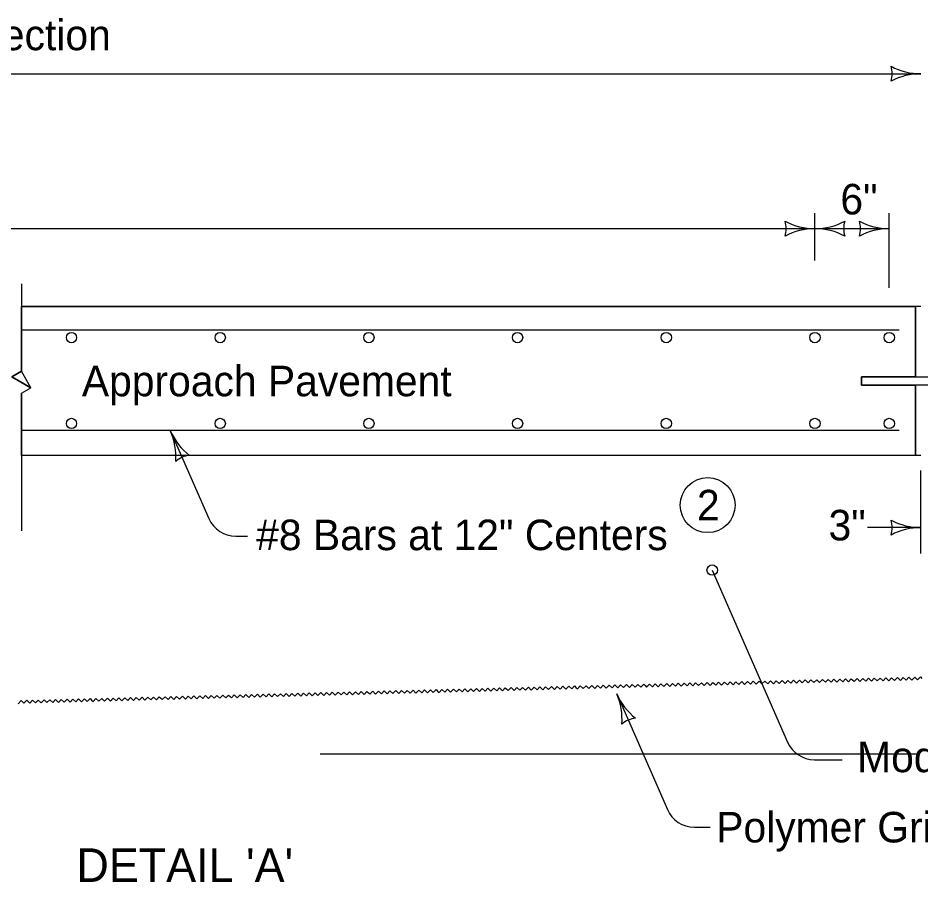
# Model space of a CAD drawing. Extents: x -2135039 to -2120895, y -2139150 to -2136566.
# Drawn here: x -2130191 to -2129599, y -2137809 to -2137243 of the extents above; entities that cross this region are included whole.
import ezdxf

# ---------------------------------------------------------------- set-up
doc = ezdxf.new("R2010")
doc.units = 0
for name, color, linetype in [('dsnStdLabel', 7, 'Continuous'), ('dsnStdLineWork', 7, 'Continuous'), ('dsnStdNote', 7, 'Continuous'), ('Level 2', 7, 'Continuous'), ('Level 3', 7, 'Continuous'), ('Level 4', 7, 'Continuous'), ('Level 5', 7, 'Continuous')]:
    doc.layers.add(name, color=color, linetype=linetype)

msp = doc.modelspace()

# ---------------------------------------------------------------- linework, layer by layer
at = {"layer": 'dsnStdLabel'}
for p, q in [((-2130208.33, -2137279.26), (-2129598.95, -2137279.26)), ((-2129668.41, -2137401.68), (-2129668.41, -2137370.66)), ((-2129619.69, -2137419.41), (-2129619.69, -2137370.66)), ((-2129668.41, -2137380.75), (-2130237.27, -2137380.75)), ((-2129619.69, -2137380.75), (-2129668.41, -2137380.75)), ((-2130090.67, -2137513.32), (-2130065.57, -2137570.65)), ((-2129598.95, -2137593.64), (-2129598.95, -2137539.26)), ((-2129598.95, -2137576.57), (-2129634, -2137576.57)), ((-2130047.94, -2137582.18), (-2130040.18, -2137582.18)), ((-2129735.72, -2137604.39), (-2129686.37, -2137717.13)), ((-2129798.28, -2137685.5), (-2129765.09, -2137761.33)), ((-2129668.74, -2137728.65), (-2129650.5, -2137728.65)), ((-2129747.46, -2137772.85), (-2129737.16, -2137772.85))]:
    msp.add_line(p, q, dxfattribs=at)
msp.add_circle((-2129735.72, -2137604.39), 3.42, dxfattribs=at)
for centre, radius, start, end in [((-2129633.79, -2137279.26), 16.05, 342.26665, 17.73335), ((-2129598.95, -2137237.71), 41.55, 241.92751, 270), ((-2129598.95, -2137320.81), 41.55, 90, 118.07249), ((-2129703.25, -2137380.75), 16.05, 342.26665, 17.73335), ((-2129668.41, -2137339.19), 41.55, 241.92751, 270), ((-2129668.41, -2137339.19), 41.55, 270, 298.07249), ((-2129633.57, -2137380.75), 16.05, 162.26665, 197.73335), ((-2129654.53, -2137380.75), 16.05, 342.26665, 17.73335), ((-2129619.69, -2137339.19), 41.55, 241.92751, 270), ((-2129668.41, -2137422.3), 41.55, 90, 118.07249), ((-2129668.41, -2137422.3), 41.55, 61.92751, 90), ((-2129619.69, -2137422.3), 41.55, 90, 118.07249), ((-2130052.6, -2137496.66), 41.55, 203.64012, 231.71261), ((-2130128.73, -2137529.98), 41.55, 355.56763, 23.64012), ((-2130076.69, -2137545.24), 16.05, 95.90677, 131.37347), ((-2130047.94, -2137562.93), 19.25, 203.64012, 270), ((-2129633.79, -2137576.57), 16.05, 342.26665, 17.73335), ((-2129598.95, -2137535.02), 41.55, 241.92751, 270), ((-2129598.95, -2137618.13), 41.55, 90, 118.07249), ((-2129760.22, -2137668.83), 41.55, 203.64012, 231.71261), ((-2129836.35, -2137702.16), 41.55, 355.56763, 23.64012), ((-2129784.31, -2137717.41), 16.05, 95.90677, 131.37347), ((-2129668.74, -2137709.41), 19.25, 203.64012, 270), ((-2129747.46, -2137753.61), 19.25, 203.64012, 270)]:
    msp.add_arc(centre, radius, start, end, dxfattribs=at)
at = {"layer": 'dsnStdLineWork'}
for p, q in [((-2130188.44, -2137416.94), (-2130188.44, -2137474.16)), ((-2129598.95, -2137431.83), (-2130188.44, -2137431.83)), ((-2129637.92, -2137483.26), (-2129637.92, -2137477.85)), ((-2129637.92, -2137477.85), (-2129559.97, -2137477.85)), ((-2129559.97, -2137483.26), (-2129637.92, -2137483.26)), ((-2130188.44, -2137488.6), (-2130188.44, -2137578.71))]:
    msp.add_line(p, q, dxfattribs=at)
for points in [[(-2130188.44, -2137488.6), (-2130182.18, -2137485), (-2130194.69, -2137477.76), (-2130188.44, -2137474.16)], [(-2129688.98, -2137677.73), (-2129688.01, -2137678.65), (-2129686.17, -2137676.72), (-2129684.23, -2137678.55), (-2129682.39, -2137676.62), (-2129680.45, -2137678.45), (-2129678.62, -2137676.52), (-2129676.67, -2137678.36), (-2129674.84, -2137676.42), (-2129672.9, -2137678.25), (-2129671.06, -2137676.32), (-2129669.12, -2137678.16), (-2129667.27, -2137676.22), (-2129665.34, -2137678.06), (-2129663.49, -2137676.12), (-2129661.56, -2137677.96), (-2129659.72, -2137676.02), (-2129657.78, -2137677.86), (-2129655.94, -2137675.92), (-2129654, -2137677.76), (-2129652.16, -2137675.83), (-2129650.22, -2137677.66), (-2129648.38, -2137675.73), (-2129646.44, -2137677.56), (-2129644.6, -2137675.63), (-2129643.64, -2137676.55)], [(-2129643.64, -2137676.55), (-2129642.67, -2137677.47), (-2129640.83, -2137675.53), (-2129638.89, -2137677.37), (-2129637.05, -2137675.43), (-2129635.11, -2137677.27), (-2129633.27, -2137675.33), (-2129631.33, -2137677.17), (-2129629.49, -2137675.23), (-2129627.55, -2137677.07), (-2129625.71, -2137675.14), (-2129623.78, -2137676.97), (-2129621.94, -2137675.04), (-2129619.99, -2137676.87), (-2129618.15, -2137674.94), (-2129616.22, -2137676.78), (-2129614.38, -2137674.84), (-2129612.44, -2137676.68), (-2129610.6, -2137674.74), (-2129608.66, -2137676.58), (-2129606.82, -2137674.64), (-2129604.88, -2137676.48), (-2129603.04, -2137674.54), (-2129601.11, -2137676.38), (-2129599.26, -2137674.44), (-2129598.3, -2137675.36)], [(-2129915.68, -2137683.65), (-2129914.72, -2137684.57), (-2129912.87, -2137682.64), (-2129910.93, -2137684.48), (-2129909.09, -2137682.54), (-2129907.16, -2137684.37), (-2129905.32, -2137682.44), (-2129903.38, -2137684.28), (-2129901.54, -2137682.33), (-2129899.6, -2137684.17), (-2129897.76, -2137682.24), (-2129895.82, -2137684.08), (-2129893.98, -2137682.14), (-2129892.05, -2137683.97), (-2129890.2, -2137682.04), (-2129888.26, -2137683.88), (-2129886.43, -2137681.94), (-2129884.49, -2137683.78), (-2129882.65, -2137681.84), (-2129880.71, -2137683.68), (-2129878.86, -2137681.74), (-2129876.93, -2137683.58), (-2129875.09, -2137681.65), (-2129873.15, -2137683.48), (-2129871.31, -2137681.55), (-2129870.34, -2137682.47)], [(-2129870.34, -2137682.47), (-2129869.37, -2137683.39), (-2129867.53, -2137681.45), (-2129865.59, -2137683.29), (-2129863.75, -2137681.35), (-2129861.81, -2137683.19), (-2129859.97, -2137681.25), (-2129858.04, -2137683.09), (-2129856.2, -2137681.15), (-2129854.26, -2137682.99), (-2129852.42, -2137681.05), (-2129850.48, -2137682.89), (-2129848.64, -2137680.96), (-2129846.7, -2137682.79), (-2129844.86, -2137680.86), (-2129842.92, -2137682.7), (-2129841.08, -2137680.76), (-2129839.14, -2137682.6), (-2129837.31, -2137680.66), (-2129835.37, -2137682.5), (-2129833.53, -2137680.56), (-2129831.59, -2137682.4), (-2129829.75, -2137680.46), (-2129827.81, -2137682.3), (-2129825.97, -2137680.36), (-2129825, -2137681.28)], [(-2129825, -2137681.28), (-2129824.03, -2137682.2), (-2129822.19, -2137680.26), (-2129820.25, -2137682.1), (-2129818.41, -2137680.16), (-2129816.47, -2137682), (-2129814.63, -2137680.07), (-2129812.7, -2137681.9), (-2129810.85, -2137679.97), (-2129808.92, -2137681.81), (-2129807.08, -2137679.87), (-2129805.14, -2137681.71), (-2129803.3, -2137679.77), (-2129801.36, -2137681.61), (-2129799.52, -2137679.67), (-2129797.58, -2137681.51), (-2129795.74, -2137679.57), (-2129793.81, -2137681.41), (-2129791.96, -2137679.48), (-2129790.03, -2137681.31), (-2129788.19, -2137679.38), (-2129786.25, -2137681.21), (-2129784.41, -2137679.28), (-2129782.47, -2137681.12), (-2129780.63, -2137679.18), (-2129779.66, -2137680.1)], [(-2129779.66, -2137680.1), (-2129778.69, -2137681.02), (-2129776.85, -2137679.08), (-2129774.91, -2137680.92), (-2129773.07, -2137678.98), (-2129771.13, -2137680.82), (-2129769.29, -2137678.89), (-2129767.35, -2137680.72), (-2129765.52, -2137678.79), (-2129763.57, -2137680.62), (-2129761.74, -2137678.68), (-2129759.8, -2137680.53), (-2129757.96, -2137678.59), (-2129756.02, -2137680.43), (-2129754.18, -2137678.49), (-2129752.24, -2137680.32), (-2129750.4, -2137678.39), (-2129748.46, -2137680.23), (-2129746.62, -2137678.29), (-2129744.68, -2137680.13), (-2129742.84, -2137678.19), (-2129740.91, -2137680.03), (-2129739.07, -2137678.09), (-2129737.13, -2137679.93), (-2129735.29, -2137678), (-2129734.32, -2137678.92)], [(-2129734.32, -2137678.92), (-2129733.35, -2137679.83), (-2129731.51, -2137677.9), (-2129729.57, -2137679.73), (-2129727.73, -2137677.8), (-2129725.79, -2137679.64), (-2129723.95, -2137677.7), (-2129722.01, -2137679.54), (-2129720.17, -2137677.6), (-2129718.23, -2137679.44), (-2129716.39, -2137677.5), (-2129714.46, -2137679.34), (-2129712.62, -2137677.4), (-2129710.68, -2137679.24), (-2129708.84, -2137677.3), (-2129706.9, -2137679.14), (-2129705.06, -2137677.21), (-2129703.12, -2137679.04), (-2129701.28, -2137677.11), (-2129699.34, -2137678.95), (-2129697.5, -2137677.01), (-2129695.57, -2137678.85), (-2129693.73, -2137676.91), (-2129691.79, -2137678.75), (-2129689.95, -2137676.81), (-2129688.98, -2137677.73)], [(-2130142.39, -2137689.57), (-2130141.42, -2137690.49), (-2130139.58, -2137688.56), (-2130137.64, -2137690.39), (-2130135.8, -2137688.46), (-2130133.86, -2137690.29), (-2130132.02, -2137688.36), (-2130130.08, -2137690.2), (-2130128.24, -2137688.26), (-2130126.3, -2137690.09), (-2130124.46, -2137688.16), (-2130122.53, -2137690), (-2130120.69, -2137688.06), (-2130118.75, -2137689.9), (-2130116.91, -2137687.96), (-2130114.97, -2137689.8), (-2130113.13, -2137687.86), (-2130111.19, -2137689.7), (-2130109.35, -2137687.77), (-2130107.41, -2137689.6), (-2130105.57, -2137687.67), (-2130103.64, -2137689.5), (-2130101.8, -2137687.57), (-2130099.86, -2137689.41), (-2130098.02, -2137687.47), (-2130097.05, -2137688.39)], [(-2130097.05, -2137688.39), (-2130096.08, -2137689.31), (-2130094.24, -2137687.37), (-2130092.3, -2137689.21), (-2130090.46, -2137687.27), (-2130088.52, -2137689.11), (-2130086.68, -2137687.17), (-2130084.74, -2137689.01), (-2130082.9, -2137687.07), (-2130080.96, -2137688.91), (-2130079.12, -2137686.98), (-2130077.18, -2137688.81), (-2130075.34, -2137686.88), (-2130073.4, -2137688.72), (-2130071.56, -2137686.78), (-2130069.62, -2137688.62), (-2130067.79, -2137686.68), (-2130065.85, -2137688.52), (-2130064.01, -2137686.58), (-2130062.07, -2137688.42), (-2130060.23, -2137686.48), (-2130058.29, -2137688.32), (-2130056.45, -2137686.38), (-2130054.51, -2137688.22), (-2130052.68, -2137686.28), (-2130051.7, -2137687.2)], [(-2130051.7, -2137687.2), (-2130050.74, -2137688.12), (-2130048.9, -2137686.18), (-2130046.96, -2137688.02), (-2130045.12, -2137686.09), (-2130043.18, -2137687.92), (-2130041.34, -2137685.99), (-2130039.4, -2137687.83), (-2130037.56, -2137685.89), (-2130035.62, -2137687.73), (-2130033.78, -2137685.79), (-2130031.85, -2137687.63), (-2130030, -2137685.69), (-2130028.07, -2137687.53), (-2130026.22, -2137685.59), (-2130024.29, -2137687.43), (-2130022.45, -2137685.49), (-2130020.51, -2137687.33), (-2130018.67, -2137685.4), (-2130016.73, -2137687.24), (-2130014.89, -2137685.3), (-2130012.95, -2137687.14), (-2130011.11, -2137685.2), (-2130009.17, -2137687.04), (-2130007.33, -2137685.1), (-2130006.37, -2137686.02)], [(-2130006.37, -2137686.02), (-2130005.4, -2137686.94), (-2130003.56, -2137685), (-2130001.62, -2137686.84), (-2129999.78, -2137684.91), (-2129997.84, -2137686.74), (-2129996, -2137684.81), (-2129994.06, -2137686.64), (-2129992.22, -2137684.71), (-2129990.28, -2137686.55), (-2129988.44, -2137684.61), (-2129986.5, -2137686.45), (-2129984.66, -2137684.51), (-2129982.72, -2137686.35), (-2129980.88, -2137684.41), (-2129978.94, -2137686.24), (-2129977.1, -2137684.31), (-2129975.16, -2137686.15), (-2129973.32, -2137684.21), (-2129971.39, -2137686.05), (-2129969.55, -2137684.11), (-2129967.61, -2137685.95), (-2129965.77, -2137684.01), (-2129963.83, -2137685.85), (-2129961.99, -2137683.91), (-2129961.02, -2137684.84)], [(-2129961.02, -2137684.84), (-2129960.05, -2137685.75), (-2129958.21, -2137683.82), (-2129956.28, -2137685.65), (-2129954.44, -2137683.72), (-2129952.49, -2137685.56), (-2129950.66, -2137683.62), (-2129948.72, -2137685.46), (-2129946.88, -2137683.52), (-2129944.94, -2137685.36), (-2129943.1, -2137683.42), (-2129941.16, -2137685.26), (-2129939.32, -2137683.32), (-2129937.38, -2137685.16), (-2129935.54, -2137683.23), (-2129933.6, -2137685.06), (-2129931.76, -2137683.13), (-2129929.83, -2137684.97), (-2129927.99, -2137683.03), (-2129926.05, -2137684.87), (-2129924.21, -2137682.93), (-2129922.27, -2137684.77), (-2129920.43, -2137682.83), (-2129918.49, -2137684.67), (-2129916.65, -2137682.74), (-2129915.68, -2137683.65)], [(-2130187.51, -2137690.87), (-2130188.57, -2137689.87), (-2130190.6, -2137691.99)], [(-2130187.73, -2137690.76), (-2130186.76, -2137691.67), (-2130184.92, -2137689.74), (-2130182.98, -2137691.58), (-2130181.14, -2137689.64), (-2130179.2, -2137691.48), (-2130177.36, -2137689.54), (-2130175.42, -2137691.38), (-2130173.58, -2137689.44), (-2130171.64, -2137691.28), (-2130169.8, -2137689.34), (-2130167.87, -2137691.18), (-2130166.03, -2137689.24), (-2130164.09, -2137691.08), (-2130162.25, -2137689.15), (-2130160.31, -2137690.98), (-2130158.47, -2137689.05), (-2130156.53, -2137690.89), (-2130154.69, -2137688.95), (-2130152.75, -2137690.79), (-2130150.91, -2137688.85), (-2130148.98, -2137690.69), (-2130147.13, -2137688.75), (-2130145.2, -2137690.59), (-2130143.36, -2137688.66), (-2130142.39, -2137689.57)]]:
    msp.add_lwpolyline(points, dxfattribs=at)
at = {"layer": 'dsnStdNote'}
msp.add_circle((-2129738.69, -2137561.86), 18, dxfattribs=at)
at = {"layer": 'Level 2'}
for p, q in [((-2129613.3, -2137447.35), (-2130188.44, -2137447.35)), ((-2129613.3, -2137513.03), (-2130188.44, -2137513.03)), ((-2129992.73, -2137724.91), (-2129601.83, -2137724.91))]:
    msp.add_line(p, q, dxfattribs=at)
at = {"layer": 'Level 3'}
for p, q in [((-2130188.44, -2137431.83), (-2129602.56, -2137431.83)), ((-2130188.44, -2137474.16), (-2130188.44, -2137431.83)), ((-2129602.56, -2137431.83), (-2129602.56, -2137477.85)), ((-2129602.56, -2137477.85), (-2129602.56, -2137431.84)), ((-2130182.19, -2137484.99), (-2130188.44, -2137474.16)), ((-2129602.56, -2137477.85), (-2129637.92, -2137477.85)), ((-2129637.92, -2137477.85), (-2129637.92, -2137483.26)), ((-2129637.92, -2137477.85), (-2129637.92, -2137483.26)), ((-2130188.44, -2137488.6), (-2130182.19, -2137484.99)), ((-2129637.92, -2137483.26), (-2129602.56, -2137483.26)), ((-2129602.56, -2137483.26), (-2129602.56, -2137529.27)), ((-2129602.56, -2137529.27), (-2129602.56, -2137483.26)), ((-2130188.44, -2137529.27), (-2130188.44, -2137488.6)), ((-2129602.56, -2137529.27), (-2130188.44, -2137529.27)), ((-2129598.94, -2137529.27), (-2130188.44, -2137529.27))]:
    msp.add_line(p, q, dxfattribs=at)
msp.add_lwpolyline([(-2130188.44, -2137474.16), (-2130194.69, -2137477.76), (-2130182.18, -2137485), (-2130188.44, -2137474.16)], dxfattribs=at)
at = {"layer": 'Level 5'}
for centre in [(-2130155.57, -2137452.12), (-2130058.14, -2137452.12), (-2129960.71, -2137452.12), (-2129863.27, -2137452.12), (-2129765.84, -2137452.12), (-2129668.41, -2137452.12), (-2129619.69, -2137452.12), (-2130155.57, -2137508.36), (-2130058.14, -2137508.36), (-2129960.71, -2137508.36), (-2129863.27, -2137508.36), (-2129765.84, -2137508.36), (-2129668.41, -2137508.36), (-2129619.69, -2137508.36)]:
    msp.add_circle(centre, 3.38, dxfattribs=at)

# ---------------------------------------------------------------- texts
at = {"layer": 'dsnStdLabel'}
for s, p in [('Double Reinforced Section', (-2130447.98, -2137263.83)), ('6"', (-2129651.73, -2137371.41)), ('Approach Pavement', (-2130148.78, -2137490.55)), ('3"', (-2129659.5, -2137584.98)), ('#8 Bars at 12" Centers', (-2130034.54, -2137591.36)), ('Modified Subbase', (-2129640.75, -2137736.83)), ('Polymer Grid', (-2129733.07, -2137782.85))]:
    msp.add_text(s, height=20, dxfattribs=at).set_placement(p)
at = {"layer": 'dsnStdNote'}
msp.add_text('2', height=20, dxfattribs=at).set_placement((-2129745.72, -2137571.86))
at = {"layer": 'Level 4'}
msp.add_text("DETAIL 'A' ", height=22, dxfattribs=at).set_placement((-2130152.36, -2137808.73))

doc.saveas('drawing.dxf')
